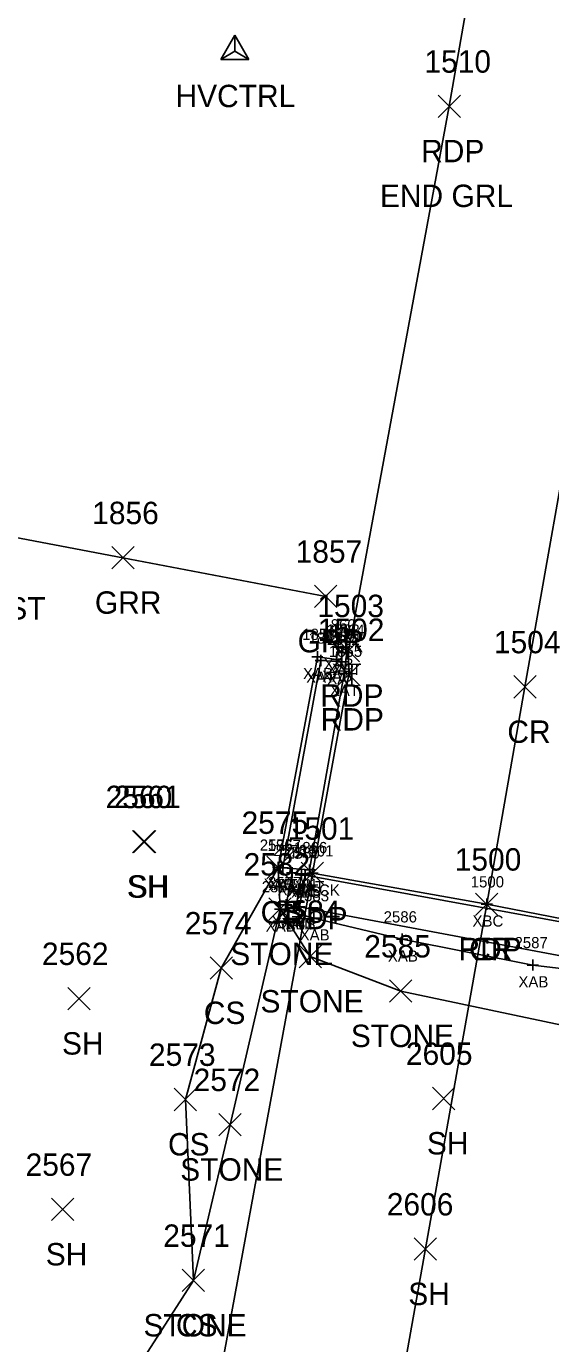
# Model space of a CAD drawing. Extents: x 1472022 to 1479249, y 777216 to 786527.
# Drawn here: x 1473693.9 to 1473740.7, y 779767.2 to 779884.8 of the extents above; entities that cross this region are included whole.
import ezdxf

# ---------------------------------------------------------------- set-up
doc = ezdxf.new("R2010")
doc.units = 0
for name, color, linetype in [('B_A', 7, 'Continuous'), ('B_I', 7, 'Continuous'), ('B_TIC', 7, 'Continuous'), ('BELB', 7, 'Continuous'), ('BSE', 7, 'Continuous'), ('BSUBM', 7, 'Continuous'), ('C_A', 7, 'Continuous'), ('CPSM', 7, 'Continuous'), ('L_A', 7, 'Continuous'), ('L_I', 7, 'Continuous'), ('L_TIC', 7, 'Continuous'), ('LASF', 7, 'Continuous'), ('LELB', 7, 'Continuous'), ('P_A', 7, 'Continuous'), ('P_C', 7, 'Continuous'), ('P_I', 7, 'Continuous'), ('P_TIC', 7, 'Continuous'), ('PET', 7, 'Continuous'), ('PRC', 7, 'Continuous'), ('R_A', 7, 'Continuous'), ('R_C', 7, 'Continuous'), ('R_I', 7, 'Continuous'), ('R_TIC', 7, 'Continuous'), ('RGR', 7, 'Continuous')]:
    doc.layers.add(name, color=color, linetype=linetype)

msp = doc.modelspace()

# ---------------------------------------------------------------- linework, layer by layer
at = {"layer": 'B_TIC'}
for p, q in [((1473721.73, 779829.4), (1473721.81, 779829.4)), ((1473719.87, 779828.55), (1473719.94, 779828.55)), ((1473719.87, 779828.55), (1473719.94, 779828.55)), ((1473720.17, 779828.22), (1473720.25, 779828.22)), ((1473720.17, 779828.22), (1473720.25, 779828.22)), ((1473721.58, 779828.31), (1473721.66, 779828.31)), ((1473722.05, 779828.93), (1473722.13, 779828.93)), ((1473722.06, 779828.1), (1473722.13, 779828.1)), ((1473722.49, 779828.92), (1473722.57, 779828.92)), ((1473722.27, 779827.04), (1473722.35, 779827.04)), ((1473716.36, 779809.73), (1473716.44, 779809.73)), ((1473716.79, 779809.69), (1473716.87, 779809.69)), ((1473716.79, 779809.69), (1473716.87, 779809.69)), ((1473717.61, 779809.25), (1473717.69, 779809.25)), ((1473717.61, 779809.25), (1473717.69, 779809.25)), ((1473718.46, 779809.1), (1473718.53, 779809.1)), ((1473718.46, 779809.1), (1473718.53, 779809.1)), ((1473718.78, 779809.03), (1473718.86, 779809.03)), ((1473718.78, 779809.03), (1473718.86, 779809.03)), ((1473719.19, 779809.51), (1473719.26, 779809.51)), ((1473719.43, 779809.21), (1473719.51, 779809.21)), ((1473716.55, 779806.01), (1473716.62, 779806.01)), ((1473717.09, 779806.39), (1473717.17, 779806.39)), ((1473717.97, 779806.21), (1473718.05, 779806.21)), ((1473718.28, 779806.2), (1473718.36, 779806.2)), ((1473735, 779806.45), (1473735.08, 779806.45)), ((1473719.57, 779805.21), (1473719.64, 779805.21)), ((1473727.45, 779803.32), (1473727.53, 779803.32)), ((1473739.12, 779801.02), (1473739.19, 779801.02))]:
    msp.add_line(p, q, dxfattribs=at)
for points in [[(1473719.87, 779828.05), (1473719.87, 779829.05)], [(1473719.87, 779828.05), (1473719.87, 779829.05)], [(1473721.23, 779829.4), (1473722.23, 779829.4)], [(1473721.73, 779828.9), (1473721.73, 779829.9)], [(1473722.05, 779828.43), (1473722.05, 779829.43)], [(1473722.49, 779828.42), (1473722.49, 779829.42)], [(1473719.37, 779828.55), (1473720.37, 779828.55)], [(1473719.37, 779828.55), (1473720.37, 779828.55)], [(1473719.67, 779828.22), (1473720.67, 779828.22)], [(1473719.67, 779828.22), (1473720.67, 779828.22)], [(1473720.17, 779827.72), (1473720.17, 779828.72)], [(1473720.17, 779827.72), (1473720.17, 779828.72)], [(1473721.08, 779828.31), (1473722.08, 779828.31)], [(1473721.55, 779828.93), (1473722.55, 779828.93)], [(1473721.55, 779828.1), (1473722.55, 779828.1)], [(1473721.58, 779827.81), (1473721.58, 779828.81)], [(1473721.99, 779828.92), (1473722.99, 779828.92)], [(1473722.05, 779827.6), (1473722.05, 779828.6)], [(1473721.77, 779827.04), (1473722.77, 779827.04)], [(1473722.27, 779826.54), (1473722.27, 779827.54)], [(1473716.36, 779809.23), (1473716.36, 779810.23)], [(1473716.79, 779809.19), (1473716.79, 779810.19)], [(1473716.79, 779809.19), (1473716.79, 779810.19)], [(1473715.86, 779809.73), (1473716.86, 779809.73)], [(1473716.29, 779809.69), (1473717.29, 779809.69)], [(1473716.29, 779809.69), (1473717.29, 779809.69)], [(1473717.11, 779809.25), (1473718.11, 779809.25)], [(1473717.11, 779809.25), (1473718.11, 779809.25)], [(1473717.61, 779808.75), (1473717.61, 779809.75)], [(1473717.61, 779808.75), (1473717.61, 779809.75)], [(1473717.95, 779809.1), (1473718.95, 779809.1)], [(1473717.95, 779809.1), (1473718.95, 779809.1)], [(1473718.28, 779809.03), (1473719.28, 779809.03)], [(1473718.28, 779809.03), (1473719.28, 779809.03)], [(1473718.45, 779808.6), (1473718.45, 779809.6)], [(1473718.45, 779808.6), (1473718.45, 779809.6)], [(1473718.68, 779809.51), (1473719.68, 779809.51)], [(1473718.78, 779808.53), (1473718.78, 779809.53)], [(1473718.78, 779808.53), (1473718.78, 779809.53)], [(1473718.93, 779809.21), (1473719.93, 779809.21)], [(1473719.18, 779809.01), (1473719.18, 779810.01)], [(1473719.43, 779808.71), (1473719.43, 779809.71)], [(1473717.09, 779805.89), (1473717.09, 779806.89)], [(1473717.97, 779805.71), (1473717.97, 779806.71)], [(1473718.28, 779805.7), (1473718.28, 779806.7)], [(1473735, 779805.95), (1473735, 779806.95)], [(1473716.04, 779806.01), (1473717.04, 779806.01)], [(1473716.54, 779805.51), (1473716.54, 779806.51)], [(1473716.59, 779806.39), (1473717.59, 779806.39)], [(1473717.47, 779806.21), (1473718.47, 779806.21)], [(1473717.78, 779806.2), (1473718.78, 779806.2)], [(1473719.57, 779804.71), (1473719.57, 779805.71)], [(1473734.5, 779806.45), (1473735.5, 779806.45)], [(1473719.07, 779805.21), (1473720.07, 779805.21)], [(1473726.95, 779803.32), (1473727.95, 779803.32)], [(1473727.45, 779802.82), (1473727.45, 779803.82)], [(1473738.61, 779801.02), (1473739.61, 779801.02)], [(1473739.11, 779800.52), (1473739.11, 779801.52)]]:
    msp.add_lwpolyline(points, dxfattribs=at)
at = {"layer": 'BELB'}
for points in [[(1473719.43, 779809.21), (1473708.22, 779748.21)], [(1473735, 779806.45), (1473724.09, 779745.09)]]:
    msp.add_lwpolyline(points, dxfattribs=at)
at = {"layer": 'BSE'}
for points in [[(1473718.78, 779809.03), (1473718.28, 779806.2), (1473748.9, 779800.48)], [(1473718.78, 779809.03), (1473749.42, 779803.44), (1473748.9, 779800.48)]]:
    msp.add_lwpolyline(points, dxfattribs=at)
at = {"layer": 'BSUBM'}
for points in [[(1473719.87, 779828.55), (1473721.58, 779828.31), (1473721.73, 779829.4)], [(1473721.73, 779829.4), (1473722.64, 779829.09)], [(1473719.87, 779828.55), (1473716.36, 779809.73), (1473716.54, 779806.01), (1473719.57, 779805.21), (1473727.45, 779803.32), (1473739.11, 779801.02), (1473748.98, 779799.83), (1473750.38, 779799.88), (1473751.85, 779803.39)], [(1473720.17, 779828.22), (1473722.05, 779828.1), (1473722.05, 779828.93), (1473722.49, 779828.92), (1473722.27, 779827.04), (1473719.18, 779809.51), (1473716.79, 779809.69)], [(1473720.17, 779828.22), (1473716.79, 779809.69)], [(1473717.61, 779809.25), (1473717.09, 779806.39), (1473717.97, 779806.21), (1473718.45, 779809.1)], [(1473717.61, 779809.25), (1473718.45, 779809.1)]]:
    msp.add_lwpolyline(points, dxfattribs=at)
at = {"layer": 'CPSM'}
for p, q in [((1473711.26, 779881.9), (1473712.51, 779884.07)), ((1473713.76, 779881.9), (1473712.51, 779884.07)), ((1473712.51, 779882.63), (1473712.51, 779884.07)), ((1473711.26, 779881.9), (1473712.51, 779882.63)), ((1473711.26, 779881.9), (1473713.76, 779881.9)), ((1473712.51, 779882.63), (1473712.51, 779882.63)), ((1473712.51, 779882.63), (1473713.76, 779881.9))]:
    msp.add_line(p, q, dxfattribs=at)
at = {"layer": 'L_TIC'}
for points in [[(1473703.36, 779811.03), (1473705.36, 779813.03)], [(1473705.36, 779811.03), (1473703.36, 779813.03)], [(1473703.45, 779811.03), (1473705.45, 779813.03)], [(1473705.45, 779811.03), (1473703.45, 779813.03)], [(1473715.36, 779808.73), (1473717.36, 779810.73)], [(1473717.36, 779808.73), (1473715.36, 779810.73)], [(1473715.54, 779805.01), (1473717.54, 779807.01)], [(1473717.54, 779805.01), (1473715.54, 779807.01)], [(1473718.24, 779800.78), (1473720.24, 779802.78)], [(1473720.24, 779800.78), (1473718.24, 779802.78)], [(1473710.29, 779799.75), (1473712.29, 779801.75)], [(1473712.29, 779799.75), (1473710.29, 779801.75)], [(1473726.32, 779797.69), (1473728.32, 779799.69)], [(1473728.32, 779797.69), (1473726.32, 779799.69)], [(1473697.58, 779797.02), (1473699.58, 779799.02)], [(1473699.58, 779797.02), (1473697.58, 779799.02)], [(1473707.09, 779788.01), (1473709.09, 779790.01)], [(1473709.09, 779788.01), (1473707.09, 779790.01)], [(1473730.16, 779788.1), (1473732.16, 779790.1)], [(1473732.16, 779788.1), (1473730.16, 779790.1)], [(1473711.08, 779785.76), (1473713.08, 779787.76)], [(1473713.08, 779785.76), (1473711.08, 779787.76)], [(1473696.12, 779778.19), (1473698.12, 779780.19)], [(1473698.12, 779778.19), (1473696.12, 779780.19)], [(1473728.51, 779774.65), (1473730.51, 779776.65)], [(1473730.51, 779774.65), (1473728.51, 779776.65)], [(1473707.8, 779771.85), (1473709.8, 779773.85)], [(1473709.8, 779771.85), (1473707.8, 779773.85)], [(1473707.8, 779771.85), (1473709.8, 779773.85)], [(1473709.8, 779771.85), (1473707.8, 779773.85)]]:
    msp.add_lwpolyline(points, dxfattribs=at)
at = {"layer": 'LASF'}
msp.add_lwpolyline([(1473674.63, 779812.66), (1473674.49, 779800.35), (1473673.09, 779784.2), (1473672.47, 779768.8), (1473686.21, 779764.41), (1473701.45, 779761.38), (1473708.8, 779772.85), (1473712.08, 779786.76), (1473716.54, 779806.01), (1473719.24, 779801.78), (1473727.32, 779798.69), (1473745.52, 779794.84), (1473745.88, 779788.84), (1473745.17, 779774.32), (1473743.47, 779755.08), (1473741.69, 779728.71)], dxfattribs=at)
at = {"layer": 'LELB'}
msp.add_lwpolyline([(1473708.8, 779772.85), (1473708.09, 779789.01), (1473711.29, 779800.75), (1473716.36, 779809.73)], dxfattribs=at)
at = {"layer": 'P_TIC'}
for points in [[(1473730.65, 779876.71), (1473732.65, 779878.71)], [(1473732.65, 779876.71), (1473730.65, 779878.71)], [(1473721.64, 779828.09), (1473723.64, 779830.09)], [(1473723.64, 779828.09), (1473721.64, 779830.09)], [(1473721.68, 779825.96), (1473723.68, 779827.96)], [(1473723.68, 779825.96), (1473721.68, 779827.96)], [(1473737.41, 779824.86), (1473739.41, 779826.86)], [(1473739.41, 779824.86), (1473737.41, 779826.86)], [(1473718.43, 779808.21), (1473720.43, 779810.21)], [(1473720.43, 779808.21), (1473718.43, 779810.21)], [(1473734, 779805.45), (1473736, 779807.45)], [(1473736, 779805.45), (1473734, 779807.45)], [(1473734, 779805.45), (1473736, 779807.45)], [(1473736, 779805.45), (1473734, 779807.45)]]:
    msp.add_lwpolyline(points, dxfattribs=at)
at = {"layer": 'PET'}
msp.add_lwpolyline([(1473746.48, 779804.23), (1473735, 779806.45), (1473719.43, 779809.21), (1473722.68, 779826.96), (1473722.64, 779829.09), (1473731.65, 779877.71), (1473741.4, 779933.53), (1473746.83, 779966.3), (1473755, 780011.96), (1473766.14, 780070.64), (1473776.66, 780127.43), (1473786.78, 780182.03), (1473796.49, 780236.66), (1473805.8, 780286.73), (1473813.14, 780328.66), (1473818.03, 780354.99), (1473826.83, 780403.57), (1473832.05, 780432.32), (1473842.07, 780489.82), (1473851.78, 780539.26), (1473858.97, 780579.12), (1473867.36, 780624.13)], dxfattribs=at)
at = {"layer": 'PRC'}
msp.add_lwpolyline([(1473735, 779806.45), (1473738.41, 779825.86), (1473746.88, 779873.78), (1473757.16, 779931.4), (1473763.53, 779963.46), (1473771.55, 780009.55), (1473781.83, 780068.07), (1473792.3, 780125.59), (1473802.3, 780178.66), (1473811.81, 780233.39), (1473821.47, 780283.6), (1473828.72, 780325.68), (1473837.7, 780374.01), (1473847.63, 780429.6), (1473858, 780486.03), (1473867.42, 780537.6), (1473874.56, 780576.61), (1473882.64, 780621.02)], dxfattribs=at)
at = {"layer": 'R_TIC'}
for points in [[(1473701.51, 779836.39), (1473703.51, 779838.39)], [(1473703.51, 779836.39), (1473701.51, 779838.39)], [(1473719.62, 779832.94), (1473721.62, 779834.94)], [(1473721.62, 779832.94), (1473719.62, 779834.94)]]:
    msp.add_lwpolyline(points, dxfattribs=at)
at = {"layer": 'RGR'}
msp.add_lwpolyline([(1473684.15, 779840.87), (1473702.51, 779837.39), (1473720.62, 779833.94)], dxfattribs=at)

# ---------------------------------------------------------------- texts
at = {"layer": 'B_A'}
for s, p in [('XAB', (1473720.45, 779827.4)), ('XAT', (1473720.76, 779826.93)), ('XAT', (1473721.19, 779826.92)), ('XAB', (1473718.59, 779826.55)), ('XAB', (1473718.59, 779826.55)), ('XAT', (1473718.87, 779826.22)), ('XAT', (1473718.87, 779826.22)), ('XAB', (1473720.3, 779826.31)), ('XAT', (1473720.76, 779826.1)), ('XAT', (1473720.98, 779825.04)), ('XAB', (1473715.08, 779807.73)), ('XAT', (1473715.49, 779807.69)), ('XAT', (1473715.49, 779807.69)), ('XAT', (1473716.31, 779807.25)), ('XAT', (1473716.31, 779807.25)), ('XAT', (1473717.16, 779807.1)), ('XAT', (1473717.16, 779807.1)), ('XDECK', (1473717.27, 779807.21)), ('XBS', (1473717.52, 779807.03)), ('XBS', (1473717.52, 779807.03)), ('XAT', (1473717.89, 779807.51)), ('XBC', (1473733.73, 779804.45)), ('XAB', (1473715.26, 779804.01)), ('XAT', (1473715.8, 779804.39)), ('XAT', (1473716.67, 779804.21)), ('XBS', (1473717.02, 779804.2)), ('XAB', (1473718.29, 779803.21)), ('XAB', (1473726.17, 779801.32)), ('XAB', (1473737.83, 779799.02))]:
    msp.add_text(s, height=1, dxfattribs=at).set_placement(p)
at = {"layer": 'B_I'}
for s, p in [('1860', (1473720.32, 779830.9)), ('1863', (1473720.68, 779830.43)), ('1864', (1473721.12, 779830.42)), ('1858', (1473718.52, 779830.05)), ('1858', (1473718.52, 779830.05)), ('1861', (1473719.08, 779829.72)), ('1861', (1473719.08, 779829.72)), ('1859', (1473720.23, 779829.81)), ('1862', (1473720.68, 779829.6)), ('1865', (1473720.9, 779828.54)), ('2575', (1473714.73, 779811.23)), ('1867', (1473715.42, 779811.19)), ('1867', (1473715.42, 779811.19)), ('2576', (1473715.95, 779810.75)), ('2576', (1473715.95, 779810.75)), ('2579', (1473716.82, 779810.6)), ('2579', (1473716.82, 779810.6)), ('2580', (1473717.11, 779810.53)), ('2580', (1473717.11, 779810.53)), ('1866', (1473717.78, 779811.01)), ('1501', (1473718.33, 779810.71)), ('1500', (1473733.57, 779807.95)), ('2582', (1473714.91, 779807.51)), ('2577', (1473715.46, 779807.89)), ('2578', (1473716.34, 779807.71)), ('2581', (1473716.93, 779807.7)), ('2583', (1473717.94, 779806.71)), ('2586', (1473725.79, 779804.82)), ('2587', (1473737.48, 779802.52))]:
    msp.add_text(s, height=1, dxfattribs=at).set_placement(p)
at = {"layer": 'C_A'}
msp.add_text('HVCTRL', height=2, dxfattribs=at).set_placement((1473707.2, 779877.63))
at = {"layer": 'L_A'}
for s, p in [('SH', (1473702.85, 779807.03)), ('SH', (1473702.94, 779807.03)), ('CS', (1473714.8, 779804.73)), ('STONE', (1473712.09, 779801.01)), ('STONE', (1473714.79, 779796.78)), ('CS', (1473709.73, 779795.75)), ('SH', (1473697.06, 779793.02)), ('STONE', (1473722.86, 779793.69)), ('CS', (1473706.53, 779784.01)), ('SH', (1473729.65, 779784.1)), ('STONE', (1473707.62, 779781.76)), ('SH', (1473695.61, 779774.19)), ('SH', (1473727.99, 779770.65)), ('STONE', (1473704.34, 779767.85)), ('CS', (1473707.24, 779767.85))]:
    msp.add_text(s, height=2, dxfattribs=at).set_placement(p)
at = {"layer": 'L_I'}
for s, p in [('2560', (1473700.96, 779815.03)), ('2561', (1473701.71, 779815.03)), ('2575', (1473713.1, 779812.73)), ('2582', (1473713.28, 779809.01)), ('2584', (1473715.99, 779804.78)), ('2574', (1473708.03, 779803.75)), ('2585', (1473724.06, 779801.69)), ('2562', (1473695.27, 779801.02)), ('2573', (1473704.83, 779792.01)), ('2605', (1473727.78, 779792.1)), ('2572', (1473708.82, 779789.76)), ('2567', (1473693.81, 779782.19)), ('2606', (1473726.07, 779778.65)), ('2571', (1473706.11, 779775.85)), ('2571', (1473706.11, 779775.85))]:
    msp.add_text(s, height=2, dxfattribs=at).set_placement(p)
at = {"layer": 'P_A'}
for s, p in [('RDP', (1473729.14, 779872.71)), ('RDP', (1473720.13, 779824.09)), ('RDP', (1473720.17, 779821.96)), ('CR', (1473736.84, 779820.86)), ('RDP', (1473716.92, 779804.21)), ('RDP', (1473732.48, 779801.45)), ('CR', (1473733.43, 779801.45))]:
    msp.add_text(s, height=2, dxfattribs=at).set_placement(p)
at = {"layer": 'P_C'}
msp.add_text('END GRL', height=2, dxfattribs=at).set_placement((1473725.46, 779868.71))
at = {"layer": 'P_I'}
for s, p in [('1510', (1473729.43, 779880.71)), ('1503', (1473719.87, 779832.09)), ('1502', (1473719.91, 779829.96)), ('1504', (1473735.64, 779828.86)), ('1501', (1473717.22, 779812.21)), ('1500', (1473732.14, 779809.45)), ('1500', (1473732.14, 779809.45))]:
    msp.add_text(s, height=2, dxfattribs=at).set_placement(p)
at = {"layer": 'R_A'}
for p in [(1473700, 779832.39), (1473718.11, 779828.94)]:
    msp.add_text('GRR', height=2, dxfattribs=at).set_placement(p)
at = {"layer": 'R_C'}
msp.add_text('SGR W/STEEL POST', height=2, dxfattribs=at).set_placement((1473669.29, 779831.87))
at = {"layer": 'R_I'}
for s, p in [('1856', (1473699.76, 779840.39)), ('1857', (1473717.93, 779836.94))]:
    msp.add_text(s, height=2, dxfattribs=at).set_placement(p)

doc.saveas('drawing.dxf')
